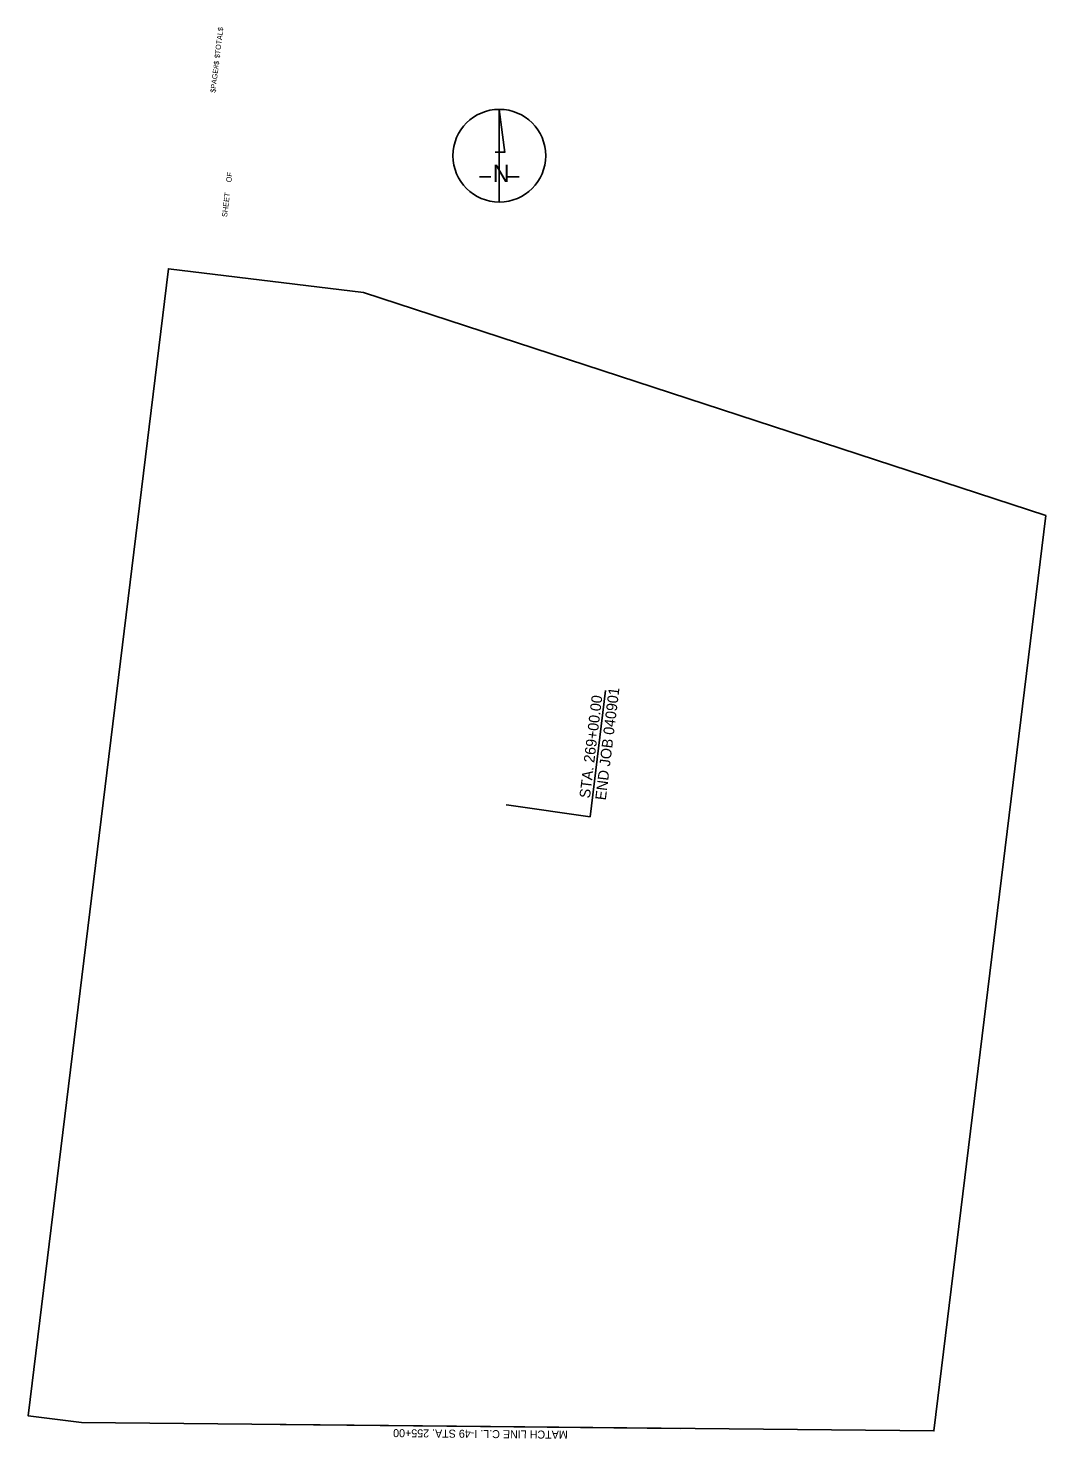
# Model space of a CAD drawing. Extents: x 631349 to 633637, y 382304 to 385478.
import ezdxf

# ---------------------------------------------------------------- set-up
doc = ezdxf.new("R2010")
doc.units = 0
for name, color, linetype in [('Copy of R_Dimension', 7, 'Continuous'), ('GN_Dimension', 7, 'Continuous'), ('R_Draft', 7, 'Continuous'), ('S_DITCHLINE', 7, 'Continuous'), ('S_ELECTRIC_UTILITIES', 7, 'Continuous')]:
    doc.layers.add(name, color=color, linetype=linetype)

msp = doc.modelspace()

# ---------------------------------------------------------------- linework, layer by layer
at = {"layer": 'Copy of R_Dimension'}
msp.add_line((632408.1, 385295), (632408.1, 385086.7), dxfattribs=at)
msp.add_lwpolyline([(633636.7, 384381.7), (632102.5, 384883), (632102.5, 384883), (631664.2, 384936.5), (631348.9, 382355.7), (631468.5, 382341.1), (633385.1, 382322.1)], close=True, dxfattribs=at)
msp.add_circle((632408.1, 385190.8), 104.2, dxfattribs=at)
at = {"layer": 'GN_Dimension'}
for p, q in [((632408.1, 385295), (632420.3, 385198)), ((632408.1, 385159.4), (632408.1, 385295)), ((632398.7, 385198.7), (632420.3, 385198.7)), ((632363.5, 385143.4), (632389.3, 385143.4)), ((632408.1, 385086.7), (632408.1, 385126.5)), ((632425.3, 385143.4), (632452.7, 385143.4))]:
    msp.add_line(p, q, dxfattribs=at)
at = {"layer": 'R_Draft'}
msp.add_line((631915.6, 382336.7), (632815.6, 382327.7), dxfattribs=at)
at = {"layer": 'S_ELECTRIC_UTILITIES'}
for p, q in [((632612.3, 383703.5), (632646.9, 383987.3)), ((632423.5, 383730.3), (632429.4, 383729.5)), ((632429.4, 383729.5), (632612.3, 383703.5))]:
    msp.add_line(p, q, dxfattribs=at)

# ---------------------------------------------------------------- texts
at = {"layer": 'Copy of R_Dimension'}
for s, p in [('OF', (631805.5, 385130.2)), ('SHEET', (631796, 385052.2))]:
    msp.add_text(s, height=12, rotation=83.0348, dxfattribs=at).set_placement(p)
at = {"layer": 'GN_Dimension'}
msp.add_text('N', height=38.8, rotation=360, dxfattribs=at).set_placement((632393.4, 385131.5))
at = {"layer": 'R_Draft'}
for s, p in [('$TOTAL$', (631779.2, 385409.5)), ('$PAGE#$', (631769.7, 385331.9))]:
    msp.add_text(s, height=11.72, rotation=83.0348, dxfattribs=at).set_placement(p)
at = {"layer": 'S_DITCHLINE'}
msp.add_text('MATCH LINE C.L. I-49 STA. 255+00', height=18, rotation=179.4304, dxfattribs=at).set_placement((632562, 382322.2))
at = {"layer": 'S_ELECTRIC_UTILITIES'}
for s, p in [('STA. 269+00.00', (632611.7, 383744.3)), ('END JOB 040901', (632647.4, 383739.9))]:
    msp.add_text(s, height=24, rotation=83.0348, dxfattribs=at).set_placement(p)

doc.saveas('drawing.dxf')
